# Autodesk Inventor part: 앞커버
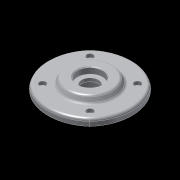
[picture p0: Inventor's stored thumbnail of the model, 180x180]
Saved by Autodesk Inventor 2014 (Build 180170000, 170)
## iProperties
Company: 한국ATC센터
Created: 2014-08
Part Number: 앞커버
Document SubType Name: Modeling
Designer: KYOUNG IL JANG
Density: 2.71 g/cm^3
Material: 알루미늄 6061
Appearance: 알루미늄 - 평지
Mass: 241.248 g
Surface Area: 231.958 cm^2
Volume: 89.0213 cm^3
Author: KYOUNG IL JANG
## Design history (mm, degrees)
sketch "스케치1"
  geometry: C1 r 30 at (0, 0) reference; A1 r 53.623 centre (0, -3.623) between (36.062, 36.062) and (-36.062, 36.062) reference; A2 r 53.623 centre (3.623, 0) between (-36.062, 36.062) and (-36.062, -36.062) reference; A3 r 53.623 centre (-3.623, 0) between (36.062, -36.062) and (36.062, 36.062) reference; A4 r 53.623 centre (0, 3.623) between (-36.062, -36.062) and (36.062, -36.062) reference; 1 further point
  node "참조9"
  node "참조14"
  node "참조15"
  node "참조16"
  node "참조17"
extrude "돌출1" new body sketch "스케치1" distance "d0" = 8; taper "d1" = 0 deg
sketch "스케치2"
  geometry: C1 r 30 at (0, 0); 1 further point
  constraints: 1 centre point, 1 coincident
  dimensions: "d2" = 60 diameter of C1
extrude "돌출2" join sketch "스케치2" distance "d3" = 7; taper "d4" = -30 deg
hole "구멍1" diameter "d7" = 20; stored, may be unused: countersink angle "d11" = 90 deg, drill point angle "d13" = 118 deg; dims "d5" = 10, "d6" = 10, "d8" = 6, "d9" = 30, "d10" = 8, "d12" = 20
sketch "스케치3"
  geometry: C1 r 1.621 at (28.284, 28.284) reference; C2 r 1.621 at (-28.284, 28.284) reference; C3 r 1.621 at (-28.284, -28.284) reference; C4 r 1.621 at (28.284, -28.284) reference; 1 further point
hole "구멍2" sketch "스케치3" at (28.284, 28.284), (28.284, -28.284), (-28.284, -28.284), (-28.284, 28.284) diameter "d14" = 4.5; stored, may be unused: countersink angle "d18" = 90 deg, drill point angle "d20" = 118 deg; dims "d15" = 6, "d16" = 8, "d17" = 4.4, "d19" = 20
extrude "돌출3" join sketch "스케치1" distance "d21" = 12; taper "d22" = 0 deg
hole "구멍3" diameter "d25" = 30; stored, may be unused: countersink angle "d29" = 90 deg, drill point angle "d31" = 0 deg; dims "d23" = 10, "d24" = 10, "d26" = 6, "d27" = 40, "d28" = 12, "d30" = 15
fillet "모깎기1" dims "d32" = 3, "d33" = 0.3
chamfer "모따기1" distance "d34" = 1; stored, may be unused: second distance "d35" = 2, angle "d36" = 45 deg
node "솔리드1"
node "참조10"
node "참조11"
node "참조12"
node "참조13"
